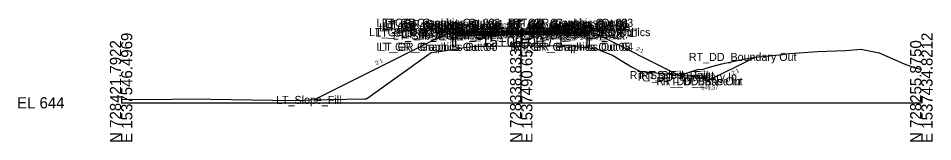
# Model space of a CAD drawing. Extents: x -26 to 1203, y -10 to 9522.
# Drawn here: x -25.7 to 202.8, y 4990.3 to 5021.1 of the extents above; entities that cross this region are included whole.
import ezdxf

# ---------------------------------------------------------------- set-up
doc = ezdxf.new("R2010")
doc.units = 0
for name, color, linetype in [('Default', 7, 'Continuous'), ('Exist Cross Section Cell', 7, 'Continuous'), ('Exist XS Center Line Elevation Label', 7, 'Continuous'), ('Exist XS Ground Line', 7, 'Continuous'), ('Old_Level_63', 7, 'Continuous'), ('Prop CMT Ditch DDE', 7, 'Continuous'), ('Prop CMT Guardrail Graphics', 7, 'Continuous'), ('Prop CMT Pvmt Course 1', 7, 'Continuous'), ('Prop CMT Pvmt Course 2', 7, 'Continuous'), ('Prop CMT Pvmt Course 3', 7, 'Continuous'), ('Prop CMT Pvmt Surface', 7, 'Continuous'), ('Prop CMT Pvmt Surface Overlay', 7, 'Continuous'), ('Prop CMT Pvmt Surface Shoulder', 7, 'Continuous'), ('Prop CMT Shld Paved Course 1', 7, 'Continuous'), ('Prop CMT Shld Paved Course 2', 7, 'Continuous'), ('Prop CMT Shld Paved Course 3', 7, 'Continuous'), ('Prop CMT Slope Grass', 7, 'Continuous'), ('Prop CMT Subgrade Earthwork', 7, 'Continuous'), ('Prop Superelevation  Arrow CELL', 7, 'Continuous'), ('Prop XS Ditch Slope Text', 7, 'Continuous'), ('Prop XS Ditch Standard Text', 7, 'Continuous'), ('Prop XS EOT Tick Mark', 7, 'Continuous'), ('Prop XS SE Text', 7, 'Continuous'), ('Prop XS Side Slope Text', 7, 'Continuous')]:
    doc.layers.add(name, color=color, linetype=linetype)

msp = doc.modelspace()

# ---------------------------------------------------------------- linework, layer by layer
at = {"layer": 'Exist Cross Section Cell'}
for p, q in [((100, 5000), (100, 5016.72)), ((0, 5000), (100, 5000)), ((100, 5000), (200, 5000))]:
    msp.add_line(p, q, dxfattribs=at)
at = {"layer": 'Exist XS Ground Line'}
msp.add_lwpolyline([(0, 5000.9), (3.61, 5000.86), (21.77, 5000.96), (22.34, 5000.94), (42.94, 5000.57), (45.78, 5000.66), (46.92, 5000.7), (60.87, 5000.95), (61.25, 5000.95), (61.68, 5001.27), (76.31, 5011.69), (77.46, 5012.54), (81.23, 5013.07), (86.24, 5013.89), (87.95, 5014.07), (98.43, 5014.23), (100, 5014.24), (100.02, 5014.24), (110.59, 5014.26), (111.92, 5014.24), (113.13, 5014.15), (118.78, 5013.43), (119.81, 5013.06), (122.82, 5011.9), (127.54, 5008.94), (129.78, 5007.82), (133.83, 5007.47), (139.78, 5006.86), (144.08, 5008.29), (145.49, 5008.42), (147.33, 5009.01), (150.11, 5009.73), (156.07, 5010.94), (158.56, 5011.41), (165.42, 5012.05), (166.28, 5012.24), (167.12, 5012.28), (174.07, 5012.77), (181.11, 5013.06), (184.8, 5013.35), (184.84, 5013.35), (184.85, 5013.35), (189.44, 5012.46), (195.67, 5009.69), (197.69, 5008.96), (200, 5008.33)], dxfattribs=at)
at = {"layer": 'Prop CMT Ditch DDE'}
for points in [[(146.39, 5005.37), (158.46, 5011.4)], [(139.39, 5006.9), (144.39, 5006.5), (146.39, 5005.37)], [(146.72, 5005.37), (146.72, 5005.37)]]:
    msp.add_lwpolyline(points, dxfattribs=at)
at = {"layer": 'Prop CMT Guardrail Graphics'}
for points in [[(82.94, 5013.96), (82.94, 5019.96)], [(82.94, 5019.96), (84.27, 5019.96), (84.54, 5019.67)], [(84.54, 5019.08), (84.27, 5018.79), (83.61, 5018.79)], [(83.61, 5018.79), (83.61, 5013.96)], [(84.54, 5019.67), (84.27, 5019.37)], [(84.27, 5019.37), (84.54, 5019.08)], [(117.09, 5019.96), (115.76, 5019.96), (115.49, 5019.66)], [(115.49, 5019.66), (115.76, 5019.37)], [(115.76, 5019.37), (115.49, 5019.08)], [(115.49, 5019.08), (115.76, 5018.79), (116.43, 5018.79)], [(116.43, 5018.79), (116.43, 5013.96)], [(117.09, 5013.96), (117.09, 5019.96)], [(83.61, 5013.96), (82.94, 5013.96)], [(116.43, 5013.96), (117.09, 5013.96)]]:
    msp.add_lwpolyline(points, dxfattribs=at)
at = {"layer": 'Prop CMT Pvmt Course 1'}
for points in [[(100, 5017.93), (89, 5017.71)], [(89, 5017.71), (89, 5017.46)], [(89, 5017.46), (100, 5017.68)], [(100, 5017.68), (100, 5017.93)], [(100, 5017.93), (111, 5017.71)], [(100, 5017.68), (100, 5017.93)], [(100, 5017.68), (100, 5017.68), (100, 5017.68)], [(111, 5017.46), (100, 5017.68)], [(100, 5017.68), (100, 5017.68), (100, 5017.68)], [(111, 5017.71), (111, 5017.46)]]:
    msp.add_lwpolyline(points, dxfattribs=at)
at = {"layer": 'Prop CMT Pvmt Course 2'}
for points in [[(100, 5017.68), (89, 5017.46)], [(89, 5017.26), (100, 5017.48)], [(89, 5017.46), (89, 5017.26)], [(100, 5017.48), (100, 5017.68)], [(100, 5017.48), (100, 5017.68)], [(100, 5017.68), (111, 5017.46)], [(111, 5017.26), (100, 5017.48)], [(111, 5017.46), (111, 5017.26)]]:
    msp.add_lwpolyline(points, dxfattribs=at)
at = {"layer": 'Prop CMT Pvmt Course 3'}
for points in [[(100, 5017.48), (89, 5017.26)], [(89, 5017.26), (89, 5016.88)], [(89, 5016.88), (100, 5017.1)], [(100, 5017.1), (100, 5017.48)], [(100, 5017.48), (111, 5017.26)], [(100, 5017.1), (100, 5017.48)], [(111, 5016.88), (100, 5017.1)], [(111, 5017.26), (111, 5016.88)]]:
    msp.add_lwpolyline(points, dxfattribs=at)
at = {"layer": 'Prop CMT Pvmt Surface'}
for points in [[(100, 5017.93), (89, 5017.71)], [(100, 5017.93), (111, 5017.71)]]:
    msp.add_lwpolyline(points, dxfattribs=at)
at = {"layer": 'Prop CMT Pvmt Surface Overlay'}
for points in [[(100, 5017.93), (89, 5017.71)], [(100, 5017.93), (111, 5017.71)]]:
    msp.add_lwpolyline(points, dxfattribs=at)
at = {"layer": 'Prop CMT Pvmt Surface Shoulder'}
for points in [[(89, 5017.71), (84.55, 5017.62)], [(111, 5017.71), (115.48, 5017.62)]]:
    msp.add_lwpolyline(points, dxfattribs=at)
at = {"layer": 'Prop CMT Shld Paved Course 1'}
for points in [[(89, 5017.71), (84.55, 5017.62), (84.3, 5017.37)], [(84.3, 5017.37), (89, 5017.46)], [(89, 5017.46), (89, 5017.71)], [(111, 5017.71), (115.48, 5017.62), (115.74, 5017.37)], [(111, 5017.46), (111, 5017.71)], [(115.74, 5017.37), (111, 5017.46)]]:
    msp.add_lwpolyline(points, dxfattribs=at)
at = {"layer": 'Prop CMT Shld Paved Course 2'}
for points in [[(89, 5017.46), (84.3, 5017.37), (84.09, 5017.16)], [(84.09, 5017.16), (89, 5017.26)], [(89, 5017.26), (89, 5017.46)], [(111, 5017.46), (115.74, 5017.37), (115.95, 5017.16)], [(111, 5017.26), (111, 5017.46)], [(115.95, 5017.16), (111, 5017.26)]]:
    msp.add_lwpolyline(points, dxfattribs=at)
at = {"layer": 'Prop CMT Shld Paved Course 3'}
for points in [[(84.09, 5017.16), (83.7, 5016.77)], [(83.7, 5016.77), (89, 5016.88)], [(89, 5017.26), (84.09, 5017.16)], [(84.09, 5017.16), (84.09, 5017.16)], [(89, 5016.88), (89, 5017.26)], [(111, 5017.26), (115.95, 5017.16)], [(111, 5016.88), (111, 5017.26)], [(116.33, 5016.77), (111, 5016.88)], [(115.95, 5017.16), (115.95, 5017.16)], [(115.95, 5017.16), (116.33, 5016.77)]]:
    msp.add_lwpolyline(points, dxfattribs=at)
at = {"layer": 'Prop CMT Slope Grass'}
for points in [[(81.54, 5017.38), (48.22, 5000.72)], [(84.54, 5017.62), (81.54, 5017.38)], [(84.55, 5017.62), (84.54, 5017.62)], [(115.48, 5017.62), (115.49, 5017.62)], [(115.49, 5017.62), (118.49, 5017.38)], [(118.49, 5017.38), (139.39, 5006.9)]]:
    msp.add_lwpolyline(points, dxfattribs=at)
at = {"layer": 'Prop CMT Subgrade Earthwork'}
for points in [[(83.7, 5016.77), (82.98, 5017.5)], [(89, 5016.88), (83.7, 5016.77)], [(100, 5017.1), (89, 5016.88)], [(100, 5017.1), (111, 5016.88)], [(111, 5016.88), (116.33, 5016.77)], [(116.33, 5016.77), (117.06, 5017.5)]]:
    msp.add_lwpolyline(points, dxfattribs=at)
at = {"layer": 'Prop Superelevation  Arrow CELL'}
for p, q in [((96.95, 5018.6), (90.95, 5018.48)), ((103.05, 5018.56), (109.04, 5018.44))]:
    msp.add_line(p, q, dxfattribs=at)
for points in [[(90.95, 5018.48), (92.44, 5019.01), (92.11, 5018.5)], [(109.04, 5018.44), (107.55, 5018.97), (107.89, 5018.46)]]:
    msp.add_lwpolyline(points, close=True, dxfattribs=at)
at = {"layer": 'Prop XS EOT Tick Mark'}
for points in [[(89, 5017.71), (89, 5018.71)], [(111, 5017.71), (111, 5018.71)]]:
    msp.add_lwpolyline(points, dxfattribs=at)

# ---------------------------------------------------------------- texts
at = {"layer": 'Default'}
msp.add_text('-', height=0.0001, dxfattribs=at).set_placement((0, 5000))
msp.add_text('-', height=0.0001, dxfattribs=at).set_placement((0, 5000))
msp.add_text('-', height=0.0001, dxfattribs=at).set_placement((0, 5000))
at = {"layer": 'Exist Cross Section Cell'}
for s, p in [('L', (90, 5016.72)), ('15+00.00 / 1', (90, 5013.92)), ('EL 644', (-26, 4998.6))]:
    msp.add_text(s, height=2.8, dxfattribs=at).set_placement(p)
for s, p in [('E 1537546.4969', (2.8, 4990)), ('E 1537490.6590', (102.8, 4990)), ('E 1537434.8212', (202.8, 4990)), ('N 728421.7922', (0, 4990)), ('N 728338.8336', (100, 4990)), ('N 728255.8750', (200, 4990))]:
    msp.add_text(s, height=2.8, rotation=90, dxfattribs=at).set_placement(p)
at = {"layer": 'Exist XS Center Line Elevation Label'}
msp.add_text('658.24', height=0.75, dxfattribs=at).set_placement((98.46, 5013.07))
at = {"layer": 'Old_Level_63'}
for s, p in [('LT_GR_Graphics Out 03', (63.84, 5018.96)), ('LT_GR_Graphics Out 02', (65.17, 5018.96)), ('RT_GR_Graphics Out 02', (96.61, 5018.96)), ('RT_GR_Graphics Out 03', (97.95, 5018.96)), ('LT_GS_OS_GR_Face_Graphics', (62, 5016.62)), ('LT_Sub_Trench_Out_DLT', (63.55, 5016.5)), ('LT_GR_Graphics Out 06', (64.46, 5017.79)), ('LT_GR_Graphics Out 09', (65.17, 5018.37)), ('LT_GR_Graphics Out 07', (65.17, 5017.79)), ('LT_GR_Graphics Out 08', (65.44, 5018.08)), ('LT_GR_Graphics Out 01', (66.01, 5018.67)), ('LT_PS1_OEOP', (75.36, 5016.62)), ('LT_PV1_OEOT', (79.74, 5016.71)), ('LT_TM_OEOT', (79.94, 5017.71)), ('RT_PV1_OEEOP_W', (87.94, 5016.68)), ('LT_PV1_OEEOP_W', (87.98, 5016.68)), ('RT_PV2_OEEOP', (89.26, 5016.68)), ('LT_PV2_OEEOP', (89.31, 5016.68)), ('RT_Seek SS Fill O', (89.44, 5016.93)), ('PV1_PGL_W', (92.58, 5016.68)), ('RT_GS_OS_GR_Face_Graphics', (92.9, 5016.62)), ('PV1_PGL', (94.47, 5016.93)), ('RT_GR_Graphics Out 08', (96.34, 5018.08)), ('RT_GR_Graphics Out 09', (96.61, 5018.37)), ('RT_GR_Graphics Out 07', (96.61, 5017.79)), ('RT_GR_Graphics Out 01', (96.91, 5018.66)), ('RT_GR_Graphics Out 06', (97.23, 5017.79)), ('RT_Sub_Trench_Out_DLT', (97.58, 5016.5)), ('RT_PV1_OEOT', (101.69, 5016.71)), ('RT_TM_OEOT', (101.9, 5017.71)), ('RT_PS1_OEOP', (106.24, 5016.62)), ('LT_Sub_Trench_Out', (67.91, 5015.77)), ('LT_PS3_Shelf_Out', (70.07, 5016.16)), ('LT_GS_OS_CTL', (70.91, 5016.38)), ('LT_PS3_OEOP', (74.32, 5016.16)), ('LT_PS2_OEOP', (74.54, 5016.37)), ('LT_Sub_OEOT', (79.08, 5015.88)), ('LT_PV2_OEOT', (79.17, 5016.46)), ('LT_PV3_OEOT', (79.17, 5016.26)), ('RT_Sub_OEEOP', (89.17, 5016.1)), ('LT_Sub_OEEOP', (89.21, 5016.1)), ('RT_PV3_OEEOP', (89.26, 5016.48)), ('LT_PV3_OEEOP', (89.31, 5016.48)), ('RT_Sub_Trench_Out', (100.49, 5015.77)), ('RT_Sub_OEOT', (101.03, 5015.88)), ('RT_PV2_OEOT', (101.13, 5016.46)), ('RT_PV3_OEOT', (101.13, 5016.26)), ('RT_PS3_Shelf_Out', (101.89, 5016.16)), ('RT_PS2_OEOP', (105.92, 5016.37)), ('RT_PS3_OEOP', (106.14, 5016.16)), ('RT_GS_OS_CTL', (107.81, 5016.38)), ('LT_GR_Graphics Out 04', (63.84, 5012.96)), ('LT_GR_Graphics Out 05', (64.5, 5012.96)), ('RT_GR_Graphics Out 05', (97.28, 5012.96)), ('RT_GR_Graphics Out 04', (97.95, 5012.96)), ('RT_DD_Boundary Out', (141.9, 5010.44)), ('RT_SS_Fill_Point', (127.1, 5005.9)), ('RT_DD_Boundary In', (129.11, 5005.5)), ('RT_Slope_Fill', (129.94, 5005.9)), ('RT_DD_Base Out', (133.76, 5004.37)), ('RT_DD_Base In', (135.39, 5004.37)), ('LT_Slope_Fill', (38.74, 4999.72))]:
    msp.add_text(s, height=2, dxfattribs=at).set_placement(p)
at = {"layer": 'Prop XS Ditch Slope Text'}
for rotation, p in [(26.5651, (152.87, 5006.88)), (333.4349, (143.89, 5005.31))]:
    msp.add_text('2:1', height=1, rotation=rotation, dxfattribs=at).set_placement(p)
at = {"layer": 'Prop XS Ditch Standard Text'}
msp.add_text('649.37', height=1, dxfattribs=at).set_placement((145.01, 5003.28))
at = {"layer": 'Prop XS SE Text'}
for rotation, p in [(1.1458, (92.73, 5018.79)), (358.8542, (103.77, 5018.86))]:
    msp.add_text('0.020', height=1, rotation=rotation, dxfattribs=at).set_placement(p)
at = {"layer": 'Prop XS Side Slope Text'}
for rotation, p in [(333.4349, (128.6, 5013.17)), (26.5651, (63.84, 5009.37))]:
    msp.add_text('2:1', height=1, rotation=rotation, dxfattribs=at).set_placement(p)

doc.saveas('drawing.dxf')
